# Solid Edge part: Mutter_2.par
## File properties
Sűrűség: 0,000 kg/m^3
Pontosság: 0,990
Author: psaghy
Last saved by: ahadarics
Revision: 77
Username: psaghy
Dokumentum tartalom típus: 0
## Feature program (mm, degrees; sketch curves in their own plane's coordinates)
base feature "unnamed BaseFeature 1"
thread "unnamed Thread 1"
chamfer "unnamed Chamfer 1"
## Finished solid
Body 1: solid body, 23 faces, 46 edges, 24 vertices.
  Faces by surface: cone 14, plane 8, cylinder 1
  Edges by curve: spline 24, circle 16, line 6
Bounding box of the edges (mm): 4.000 x 8.083 x 7.000, from (0, -4.0415, -3.5) to (4, 4.0415, 3.5).
Cylindrical faces by radius (mm): R1.621 x1
Conical faces (half-angle, radius in mm at the cone's reference point): 45 deg R1.621 x1, 45 deg R1.821 x1, 60 deg R3.7707 x12
Planar faces by outward normal: +x 1, +z 1, -x 1, -z 1, oblique 4
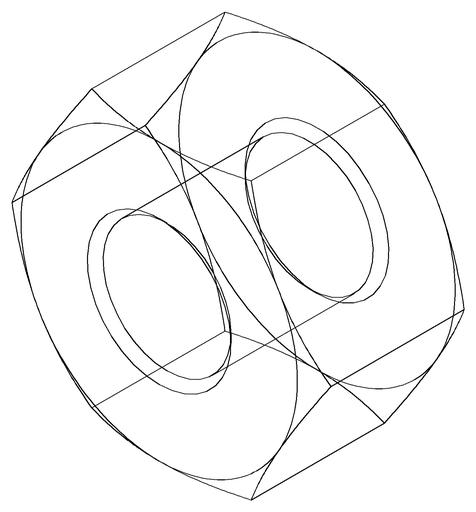
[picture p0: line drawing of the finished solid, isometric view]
